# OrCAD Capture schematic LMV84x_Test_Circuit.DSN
size A; title: LMV84x CMOS Input, RRIO, Low Power, Wide Supply Range,; rev: 1.3; note: Datasheet: SNOSAT1I   EVM: N/A
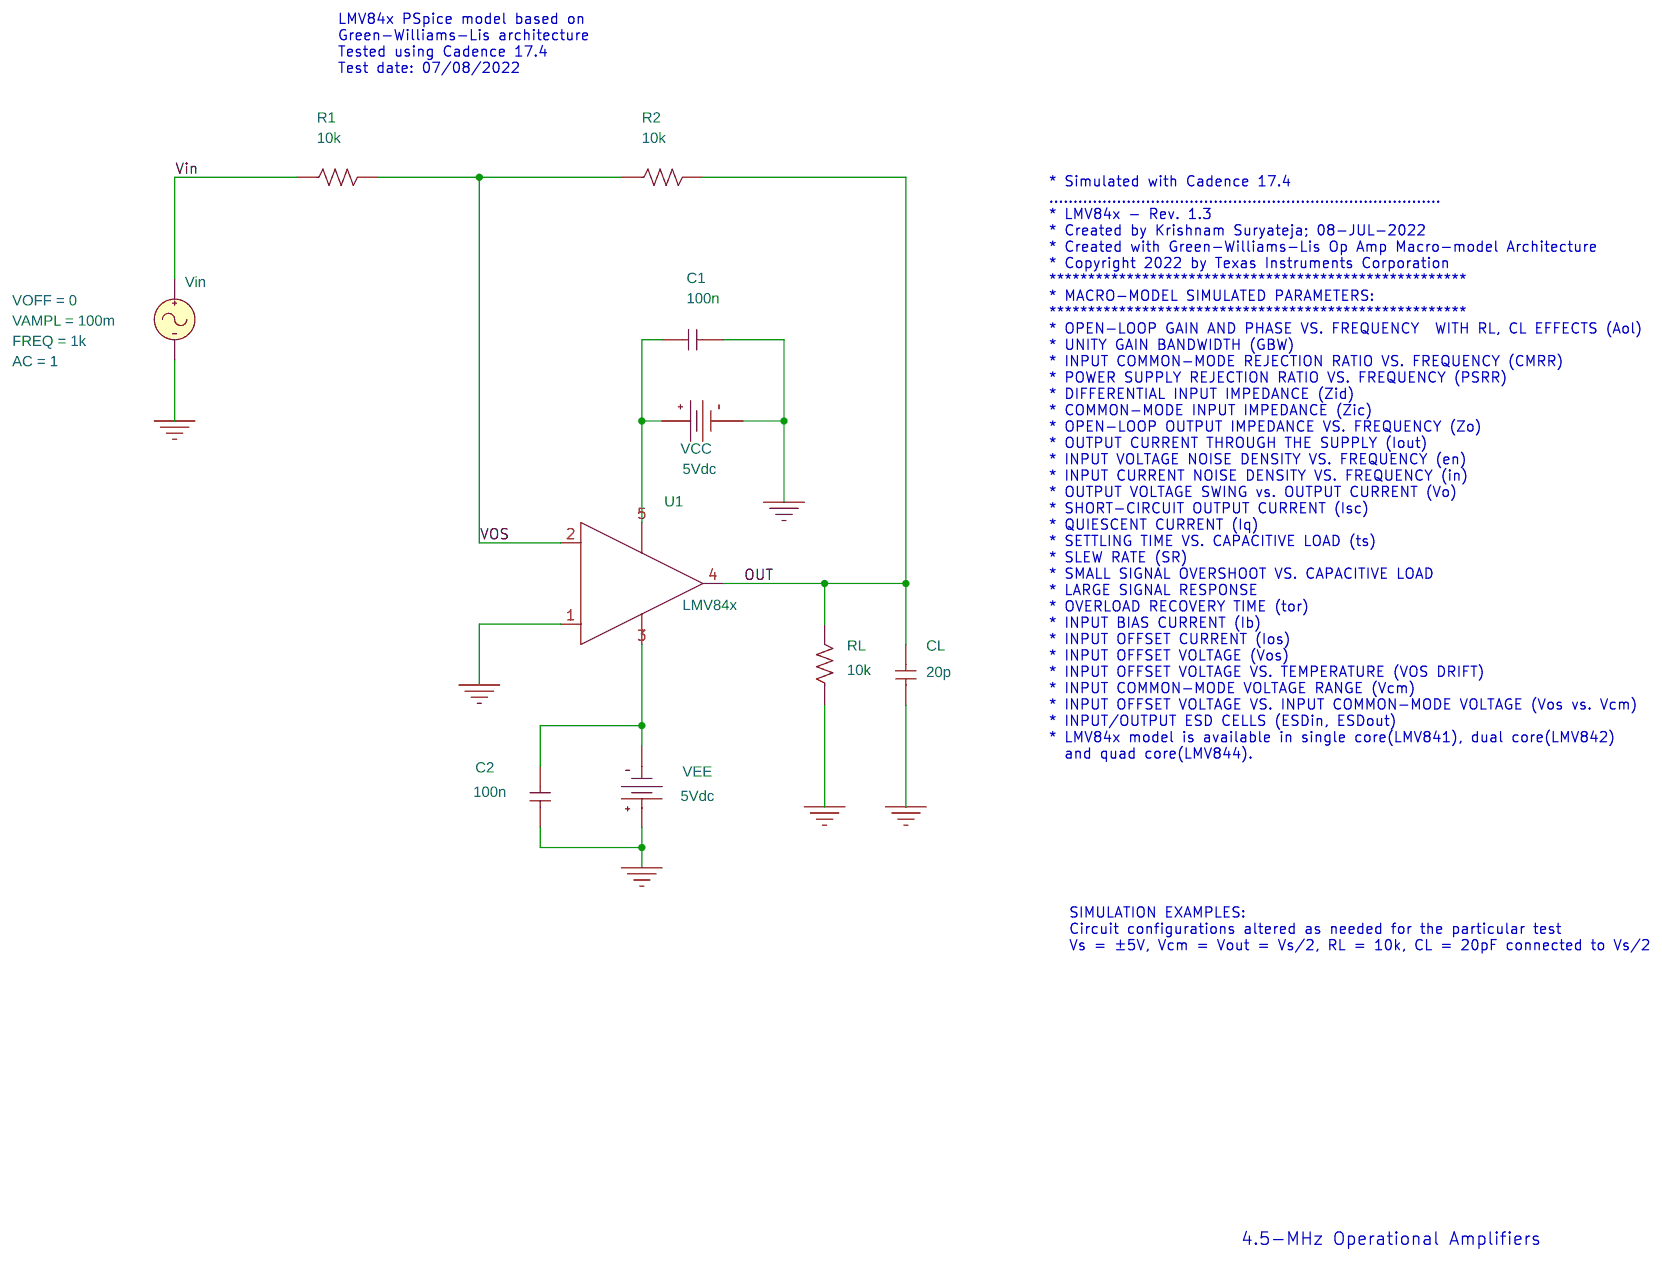
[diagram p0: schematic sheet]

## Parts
C1  100n  [cap196]
C2  100n  [cap196]
CL  20p  [cap196]
R1  10k  [AXRC05]
R2  10k  [AXRC05]
RL  10k  [AXRC05]
U1  LMV84x
VCC  VDC
VEE  VDC
Vin  VSIN

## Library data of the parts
C1 C2 CL = C
R1 R2 RL = R
U1 = LMV84x
VCC VEE = VDC: DC: 5Vdc
Vin = VSIN: AC: 1; FREQ: 1k; VAMPL: 100m; VOFF: 0

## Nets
Vin: R1.1 Vin.1(+)
0: C1.2 C2.1 CL.2 RL.1 U1.1(+) VCC.1(-) VEE.0(+) Vin.2(-)
OUT: CL.1 R2.2 RL.2 U1.4(OUT)
VOS: R1.2 R2.1 U1.2(-)
N27303: C1.1 U1.5(V+) VCC.0(+)
N27354: C2.2 U1.3(V-) VEE.1(-)

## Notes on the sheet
- LMV84x PSpice model based on
  Green-Williams-Lis architecture
  Tested using Cadence 17.4
  Test date: 07/08/2022
- * Simulated with Cadence 17.4
  .................................................................................
  * LMV84x - Rev. 1.3
  * Created by Krishnam Suryateja; 08-JUL-2022
  * Created with Green-Williams-Lis Op Amp Macro-model Architecture
  * Copyright 2022 by Texas Instruments Corporation
  ******************************************************
  * MACRO-MODEL SIMULATED PARAMETERS:
  ******************************************************
  * OPEN-LOOP GAIN AND PHASE VS. FREQUENCY  WITH RL, CL EFFECTS (Aol)
  * UNITY GAIN BANDWIDTH (GBW)
  * INPUT COMMON-MODE REJECTION RATIO VS. FREQUENCY (CMRR)
  * POWER SUPPLY REJECTION RATIO VS. FREQUENCY (PSRR)
  * DIFFERENTIAL INPUT IMPEDANCE (Zid)
  * COMMON-MODE INPUT IMPEDANCE (Zic)
  * OPEN-LOOP OUTPUT IMPEDANCE VS. FREQUENCY (Zo)
  * OUTPUT CURRENT THROUGH THE SUPPLY (Iout)
  * INPUT VOLTAGE NOISE DENSITY VS. FREQUENCY (en)
  * INPUT CURRENT NOISE DENSITY VS. FREQUENCY (in)
  * OUTPUT VOLTAGE SWING vs. OUTPUT CURRENT (Vo)
  * SHORT-CIRCUIT OUTPUT CURRENT (Isc)
  * QUIESCENT CURRENT (Iq)
  * SETTLING TIME VS. CAPACITIVE LOAD (ts)
  * SLEW RATE (SR)
  * SMALL SIGNAL OVERSHOOT VS. CAPACITIVE LOAD
  * LARGE SIGNAL RESPONSE
  * OVERLOAD RECOVERY TIME (tor)
  * INPUT BIAS CURRENT (Ib)
  * INPUT OFFSET CURRENT (Ios)
  * INPUT OFFSET VOLTAGE (Vos)
  * INPUT OFFSET VOLTAGE VS. TEMPERATURE (VOS DRIFT)
  * INPUT COMMON-MODE VOLTAGE RANGE (Vcm)
  * INPUT OFFSET VOLTAGE VS. INPUT COMMON-MODE VOLTAGE (Vos vs. Vcm)
  * INPUT/OUTPUT ESD CELLS (ESDin, ESDout)
  * LMV84x model is available in single core(LMV841), dual core(LMV842)
    and quad core(LMV844).
- SIMULATION EXAMPLES:
  Circuit configurations altered as needed for the particular test
  Vs = ±5V, Vcm = Vout = Vs/2, RL = 10k, CL = 20pF connected to Vs/2
- 4.5-MHz Operational Amplifiers
